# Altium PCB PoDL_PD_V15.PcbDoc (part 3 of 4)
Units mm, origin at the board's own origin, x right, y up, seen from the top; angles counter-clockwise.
Board outline 145 x 75 mm, 4 copper layers (Top Layer, Signal Layer 2, Signal Layer 3, Bottom Layer), stack 1.586 mm thick; 346 components, 228 nets, 1035 pads, 619 vias.
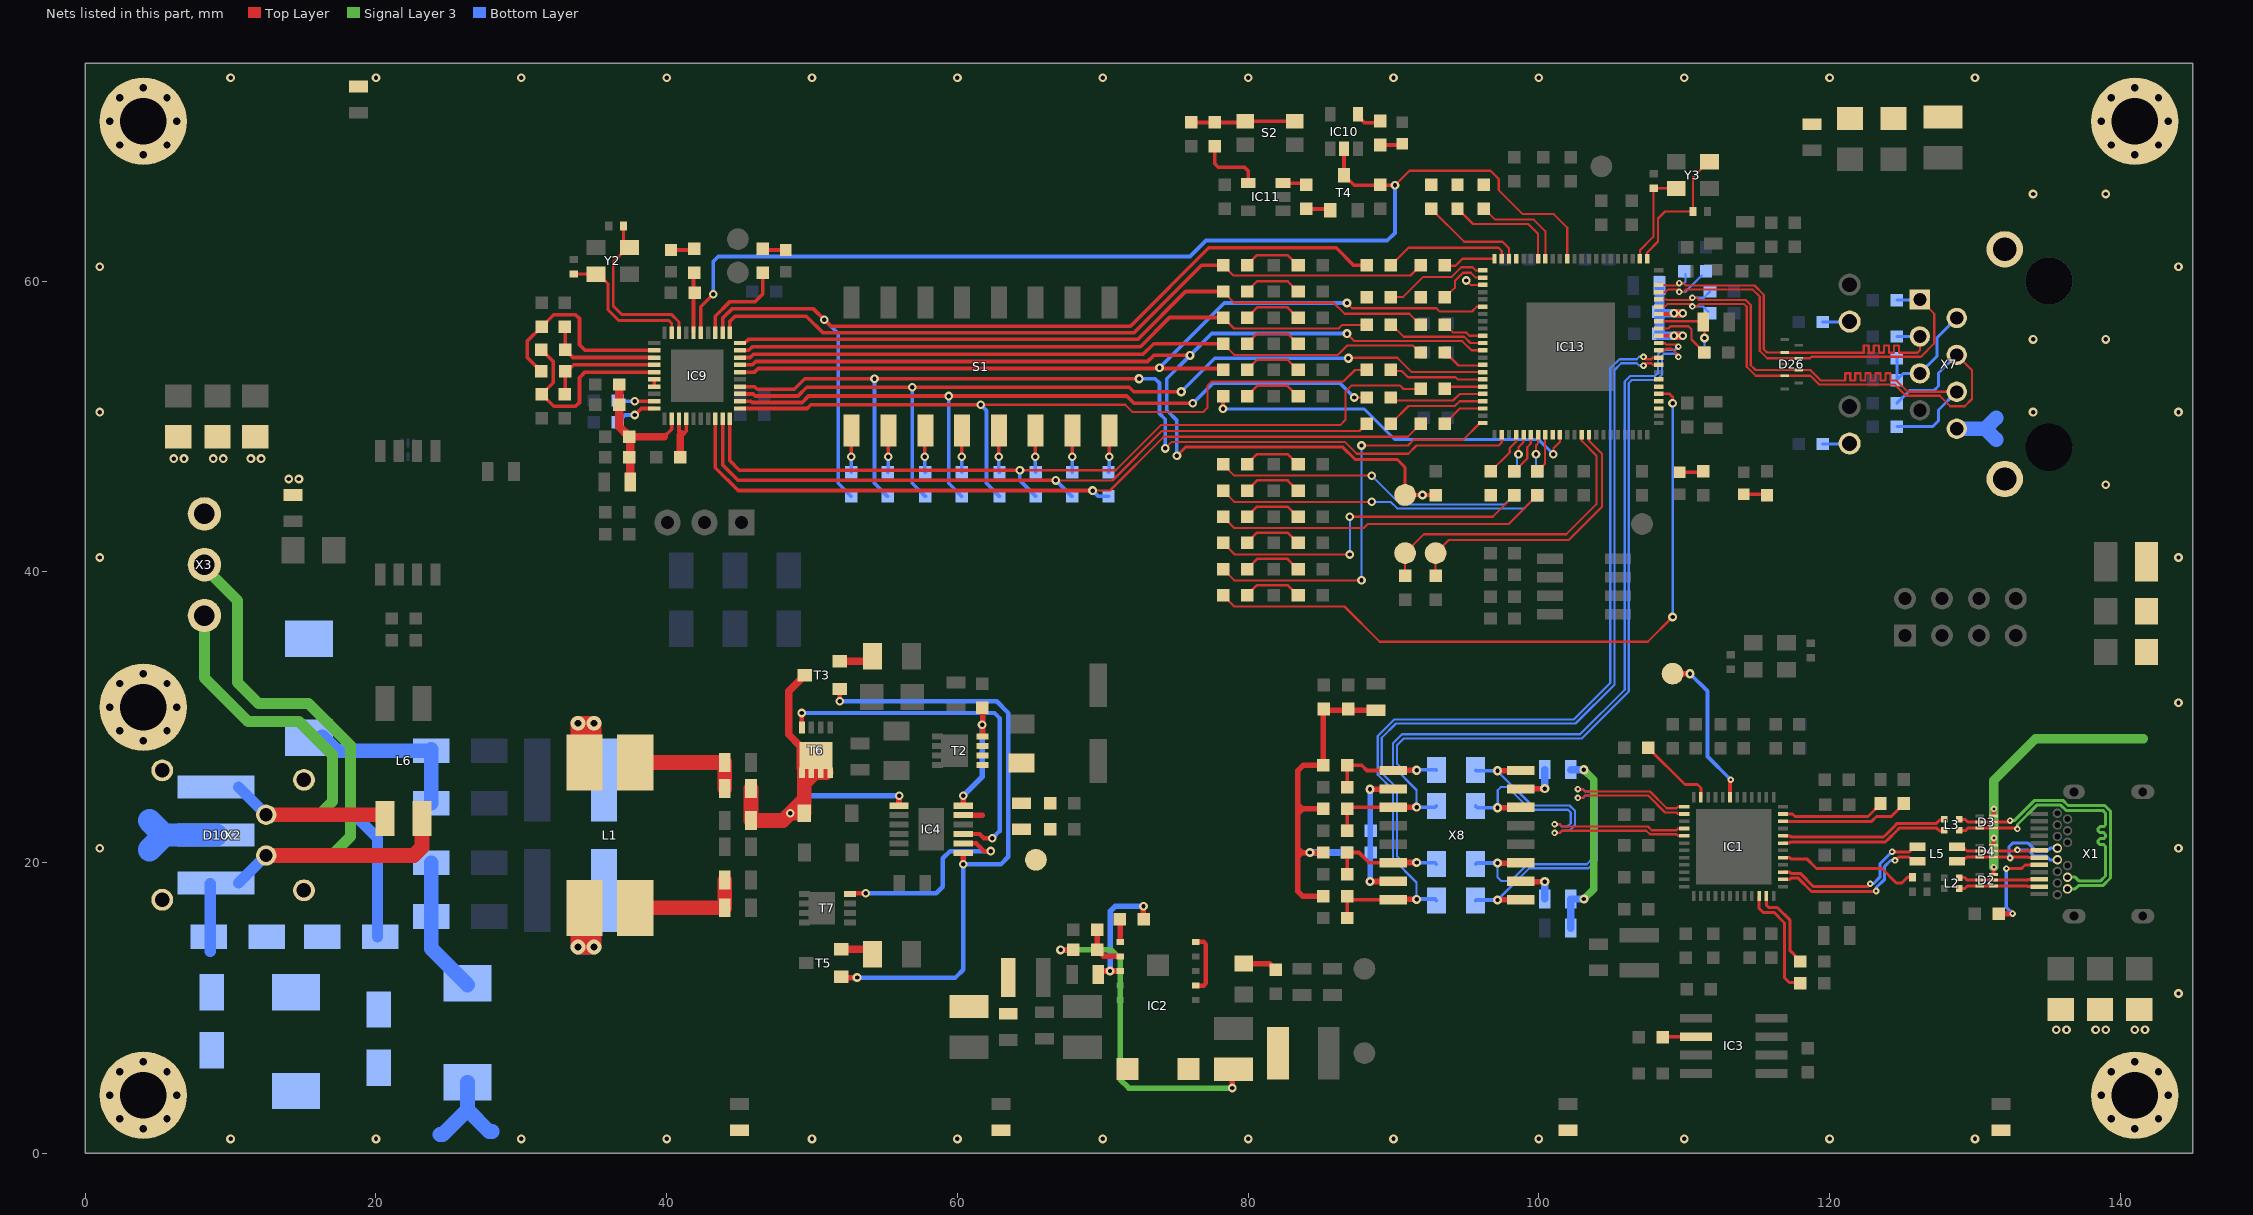
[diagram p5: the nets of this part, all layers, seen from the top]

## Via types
v1: diameter 0.6, hole 0.3, Top Layer to Bottom Layer, tented both sides, 350 vias
v2: diameter 0.45, hole 0.2, Top Layer to Bottom Layer, tented both sides, 137 vias
v3: diameter 0.635, hole 0.3, Top Layer to Bottom Layer, tented both sides, 77 vias
v4: diameter 1.016, hole 0.508, Top Layer to Bottom Layer, 40 vias
v5: diameter 1.016, hole 0.457, Top Layer to Bottom Layer, tented both sides, 8 vias
v6: diameter 0.762, hole 0.381, Top Layer to Bottom Layer, tented both sides, 7 vias

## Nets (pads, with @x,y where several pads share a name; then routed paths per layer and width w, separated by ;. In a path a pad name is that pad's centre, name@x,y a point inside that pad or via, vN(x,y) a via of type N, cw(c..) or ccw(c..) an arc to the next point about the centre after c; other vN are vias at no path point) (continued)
NetC53_1: C53.1 C54.1 FB8.1 R153.2 R154.2 R155.2 R156.2 R157.2 | length 26.9
  Top Layer w0.381: C53.1@85.075,30.449 C53.1@85.2,30.575 85.275,30.5 FB8.1@88.8,30.5 ; R154.2@85.175,17.7 83.75,17.7 83.4,18.05 83.4,20.4 ; R155.2@85.175,20.7 v3(84.25,20.7) 83.7,20.7 ; R156.2@85.175,23.7 83.75,23.7 ; C53.1@85.175,30.449 R157.2@85.175,26.7 83.779,26.7 83.4,26.321 83.4,24.05 ; 83.4,20.4 83.4,21 ; 83.4,20.4 83.7,20.7 ; 83.4,21 83.4,23.35 ; 83.4,21 83.7,20.7 ; 83.4,23.35 83.4,24.05 ; 83.4,23.35 83.75,23.7 ; 83.4,24.05 83.75,23.7
  Bottom Layer w0.508: v3(84.25,20.7) R153.2@86.775,20.7
NetC55_2: C55.2 IC9.8 Y2.1 | length 11.9
  Top Layer w0.203: C55.2@37.025,63.8 37.025,62.75 Y2.1@37.45,62.325 37.325,62.325 36.325,61.325 36.325,58.3 36.925,57.7 40.35,57.7 40.85,57.2 IC9.8@40.85,56.45
NetC56_2: C56.2 IC9.9 Y2.3 | length 10
  Top Layer w0.203: C56.2@33.6,60.5 35.3,60.5 Y2.3@35.325,60.475 ; Y2.3@35.15,60.475 Y2.3@35.325,60.475 ; IC9.9@40.35,56.45 40.35,57.1 40.15,57.3 36.7,57.3 35.95,58.05 35.95,59.85 Y2.3@35.325,60.475
NetC57_1: C57.1 C58.1 C63.1 C64.1 FB1.2 IC9.16 IC9.17 IC9.22 | length 11.4
  Top Layer w0.254: IC9.17@39.15,52.75 IC9.16@39.15,53.25 ; 39.825,49.3 40.35,49.825 IC9.22@40.35,50.55
  Top Layer w0.508: C63.1@37.426,49.3 39.825,49.3
  Top Layer w0.584: C58.1@36.726,52.9 C57.1@36.726,51.5 36.726,50 C63.1@37.426,49.3 37.5,49.226 FB1.2@37.5,46.2
NetC59_1: C59.1 IC9.19 | length 2.5
  Top Layer w0.254: v1(37.8,51.75) IC9.19@39.15,51.75
  Bottom Layer w0.254: C59.1@36.626,51.8 36.676,51.75 v1(37.8,51.75)
NetC60_1: C60.1 IC9.20 | length 2.9
  Top Layer w0.254: v1(37.8,50.8) 38.25,51.25 IC9.20@39.15,51.25
  Bottom Layer w0.254: C60.1@36.626,50.3 37.126,50.8 v1(37.8,50.8)
NetC65_1: C65.1 IC9.23 IC9.24 | length 4
  Top Layer w0.254: IC9.23@40.85,50.55 40.85,49.65 41,49.5 41.174,49.5 41.35,49.676 IC9.24@41.35,50.55
  Top Layer w0.508: C65.1@40.926,47.9 40.926,49.426 41,49.5
NetC77_1: C77.1 FB2.2 IC13.81 | length 5.1
  Top Layer w0.152: IC13.81@108.258,57.25 FB2.2@111.25,57.25 ; FB2.2@111.374,57.3 111.4,57.275 v1(111.4,56.1)
  Bottom Layer w0.152: C77.1@111.4,55.225 v1(111.4,56.1)
NetC80_1: C80.1 C81.1 FB5.1 IC13.79 IC13.82 | length 9.9
  Top Layer w0.254: IC13.79@108.308,56.25 v1(109.3,56.25) ; IC13.82@108.308,57.75 v1@109.3,57.75
  Top Layer w0.6: v1(109.3,56.25) v1(109.9,56.25) ; v1(109.3,57.8) v1(109.9,57.8)
  Bottom Layer w0.6: C81.1@108.225,56.3 108.275,56.25 v1(109.3,56.25) v1(109.9,56.25) ; C80.1@108.225,57.8 108.275,57.75 C80.1@108.3,57.75 ; C80.1@108.3,57.8 v1(109.3,57.8) v1(109.9,57.8)
  Bottom Layer w0.7: C81.1@108.225,56.3 108.3,56.375 108.3,57.75 FB5.1@108.3,59.6
NetC82_2: C82.2 IC13.1 Y3.1 | length 9.6
  Top Layer w0.152: IC13.1@107.45,61.55 107.45,61.983 108.203,62.736 108.203,64.32 108.683,64.8 C82.2@110.6,64.8 110.6,67.15 111.675,68.225 Y3.1@111.75,68.225
NetC83_2: C83.2 IC13.2 Y3.3 | length 6.8
  Top Layer w0.152: IC13.2@106.95,61.55 106.95,62.123 107.879,63.052 C83.2@107.879,66.4 ; C83.2@107.9,66.4 109.425,66.4 Y3.3@109.45,66.375
NetC89_1: C89.1 R81.1 X7.P2 X7.P5 | length 8.2
  Bottom Layer w0.203: R81.1@124.625,54.7 C89.1@124.625,53.2 125.09,53.665 X7.P5@126.21,53.665 ; X7.P5@126.145,53.6 X7.P5@126.21,53.665 ; X7.P2@128.75,57.475 127.4,56.125 127.4,54.855 X7.P5@126.21,53.665
NetC96_1: C96.1 FB10.1 IC4.11 R13.1 T2.1 T2.2 T2.3 | length 1.3
  Top Layer w0.381: IC4.11@60.416,23.275 61.7,23.275
NetC98_1: C98.1 R153.1 X8.10 X8.15 | length 9.5
  Top Layer w0.381: v3(88.388,18.706) X8.15@89.97,18.706 ; v3(88.388,25.056) X8.10@89.97,25.056
  Bottom Layer w0.381: v3(88.388,18.706) v3(88.388,25.056)
NetC103_1: C103.1 R158.1 R159.1 | length 13.3
  Signal Layer 3 w0.508: v3(103.1,17.5) 103.775,18.175 103.775,25.725 v3(103.1,26.4)
  Bottom Layer w0.508: C103.1@102.2,15.5 R158.1@102.2,17.5 ; R158.1@102.2,17.5 v3(103.1,17.5) ; R159.1@102.2,26.4 v3(103.1,26.4)
NetC106_1: C106.1 IC2.6 IC2.7 L12.1 R24.2 | length 22.7
  Top Layer w0.381: v1(67.1,14) R24.2@67.974,14 ; v1(78.9,4.5) C106.1@78.9,5.7
  Signal Layer 3 w0.381: v1(67.1,14) 70.6,14 71.2,13.4 71.2,5.1 71.8,4.5 v1(78.9,4.5)
NetC107_1: C107.1 IC2.3 R25.2 | length 9
  Top Layer w0.381: C107.1@69.7,12.3 69.95,12.55 v1(70.5,12.55) IC2.3@71.2,12.55 ; R25.2@72.8,16.125 v1(72.8,17)
  Bottom Layer w0.381: v1(70.5,12.55) 70.5,16.656 70.844,17 v1(72.8,17)
NetD1_1: D1.1 FB9.2 IC4.1 R3.1 T3.3 T6.mb | length 30.3
  Top Layer w0.381: IC4.1@55.984,23.925 55.984,24.584 v1(56,24.6)
  Top Layer w0.508: T6.mb@49.2,26.5 49.2,28.023 48.4,28.823 48.4,31.8 T3.3@49.5,32.9
  Top Layer w1.016: FB9.2@45.8,25.1 R3.1@45.8,22.9 48,22.9 v1(48.5,23.4) ; T6.mb@50.275,27.37 T6.mb@49.46,26.555 ; 50.97,26.19 T6.mb@50.6,26.19 50.191,26.19 ; v1(48.5,23.4) 49.4,24.3 49.46,24.3 ; v1(48.5,23.4) D1.1@49.46,23.4 49.46,24.3 ; 49.46,24.3 49.46,25.459 ; 49.46,25.459 50.191,26.19 ; 49.46,25.459 T6.mb@49.46,26.555 ; T6.mb@49.46,26.555 49.825,26.19 T6.mb@49.95,26.19 50.191,26.19
  Bottom Layer w0.381: v1(48.5,23.4) 49.7,24.6 v1(56,24.6)
NetD5_2: D5.2 R4.2 | length 2.4
  Top Layer w0.381: D5.2@79.7,13.05 81.476,13.05 R4.2@81.9,12.625
NetD11_1: D11.1 D13.2 D16.1
NetD12_2: D12.2 D13.1 D15.2
NetD14_2: D14.2 D18.1 D19.2 | length 9.4
  Bottom Layer w1.016: D14.2@23.8,20 D18.1@23.8,16.3 23.8,14.096 D19.2@26.3,11.596
NetD20_2: D20.2 D21.1 D31.2 | length 11.7
  Bottom Layer w1.016: D31.2@16.3,28.65 17.25,27.7 D20.2@23.8,27.7 23.8,27.8 D21.1@23.8,24.1
NetD23_1: D23.1 R62.1 | length 1.6
  Top Layer w0.254: D23.1@40.3,62.15 41.825,62.15 R62.1@41.9,62.226
NetD24_1: D24.1 R63.2 | length 1.6
  Top Layer w0.254: R63.2@46.6,62.226 46.676,62.15 D24.1@48.2,62.15
NetD25_2: D25.2 R74.2 | length 1.5
  Top Layer w0.254: R74.2@89.1,69.374 90.525,69.374 D25.2@90.6,69.45
NetD27_2: D27.2 R92.2 | length 1.6
  Top Layer w0.25: D27.2@114.1,45.35 115.624,45.35 R92.2@115.7,45.275
NetD28_2: D28.2 R93.2 | length 1.6
  Top Layer w0.25: D28.2@109.7,46.85 111.224,46.85 R93.2@111.3,46.926
NetIC1_23: IC1.23 R5.2 | length 5.8
  Top Layer w0.203: IC1.23@115.65,17.7 115.65,17.086 115.811,16.925 116.399,16.925 117.288,16.036 117.288,13.942 R5.2@117.975,13.255
NetIC1_35: IC1.35 R6.2 | length 7.2
  Top Layer w0.203: IC1.35@116.8,23.35 117.45,23.35 117.62,23.18 122.651,23.18 R6.2@123.525,24.055
NetIC1_47: IC1.47 R7.1 | length 5.4
  Top Layer w0.2: R7.1@107.526,27.9 110.045,25.381 110.905,25.381 111.15,25.135 IC1.47@111.15,24.5
NetIC2_1: IC2.1 R25.1 | length 1.5
  Top Layer w0.381: IC2.1@71.2,14.55 R25.1@71.2,16.074
NetIC2_2: IC2.2 R24.1 R26.1 | length 3.2
  Top Layer w0.381: R26.1@69.625,15.4 R24.1@69.625,14 70.076,13.55 IC2.2@71.2,13.55
NetIC2_9: IC2.9 IC2.12 | length 4.2
  Top Layer w0.305: IC2.9@76.4,11.55 76.95,11.55 77.1,11.7 77.1,14.4 76.95,14.55 IC2.12@76.4,14.55
NetIC3_6: IC3.6 R17.1 | length 2.2
  Top Layer w0.254: R17.1@108.56,8.035 IC3.6@110.8,8.035
NetIC4_7: IC4.7 T3.1 T5.1 | length 42.5
  Top Layer w0.305: v1(51.9,31.1) T3.1@51.9,31.95
  Top Layer w0.381: T5.1@52.15,12.1 v1(53.1,12.1) ; v1(60.4,19.9) 60.4,20.659 IC4.7@60.416,20.675
  Bottom Layer w0.305: v1(51.9,31.1) 62.7,31.1 63.5,30.3 63.5,20.405 62.995,19.9 v1(60.4,19.9) 60.4,12.635 59.865,12.1 v1(53.1,12.1)
NetIC4_8: IC4.8 T7.4 | length 14.1
  Top Layer w0.305: T7.4@52.6,17.9 v1(53.7,17.9) ; IC4.8@60.416,21.325 61.3,21.325 61.825,20.8 v1(62.3,20.8)
  Bottom Layer w0.305: v1(53.7,17.9) 58.545,17.9 59,18.355 59,20.3 59.5,20.8 v1(62.3,20.8)
NetIC4_9: IC4.9 T6.4 | length 25.3
  Top Layer w0.305: T6.4@49.3,29.3 v1(49.3,30.3) ; IC4.9@60.416,21.975 61.527,21.975 61.827,21.675 v1(62.4,21.675)
  Bottom Layer w0.305: v1(49.3,30.3) 62.553,30.3 62.9,29.953 62.9,22.175 v1(62.4,21.675)
NetIC4_12: IC4.12 R10.1 T2.4 | length 8.1
  Top Layer w0.381: IC4.12@60.4,23.941 v1(60.4,24.6) ; R10.1@61.7,30.675 61.73,30.645 T2.4@61.73,28.675
  Bottom Layer w0.381: v1(60.4,24.6) 61.7,25.9 v1(61.7,29.5)
NetIC9_3: IC9.3 R63.1 | length 6.5
  Top Layer w0.254: IC9.3@43.35,56.45 43.35,57.6 44.35,58.6 46.1,58.6 46.6,59.1 R63.1@46.6,60.575
NetIC9_6: IC9.6 R61.1 R62.2 | length 4.1
  Top Layer w0.254: IC9.6@41.85,56.45 41.85,60.525 R62.2@41.9,60.575
NetIC9_12: IC9.12 R64.2 R66.1 | length 14.1
  Top Layer w0.254: R66.1@31.375,53.8 30.4,54.775 30.4,55.875 R64.2@31.4,56.875 32.225,57.7 33.735,57.7 34,57.435 34,55.625 34.375,55.25 IC9.12@39.15,55.25
NetIC9_13: IC9.13 R65.2 R67.1 | length 7.7
  Top Layer w0.254: R65.2@33,56.875 33.026,56.849 R67.1@33.026,55.3 ; R67.1@33.2,55.1 33.55,54.75 IC9.13@39.15,54.75
NetIC9_14: IC9.14 R66.2 R68.2 | length 7.9
  Top Layer w0.254: R68.2@33,52.226 33.026,52.251 R66.2@33.026,53.8 33.15,53.8 33.6,54.25 IC9.14@39.15,54.25
NetIC9_15: IC9.15 R67.2 R69.2 | length 13.8
  Top Layer w0.254: R67.2@31.375,55.3 32.2,54.474 32.2,53.026 R69.2@31.4,52.226 32.226,51.4 33.735,51.4 34,51.665 34,53.364 34.386,53.75 IC9.15@39.15,53.75
NetIC10_4: IC10.4 R74.1 | length 1.9
  Top Layer w0.254: IC10.4@87.55,71.5 87.55,71.35 88,70.9 88.975,70.9 R74.1@89.1,71.025
NetIC11_3: IC11.3 R76.1 | length 1.7
  Top Layer w0.254: IC11.3@82.4,66.75 83.875,66.75 R76.1@84,66.626
NetIC11_4: IC11.4 R75.2 | length 4.5
  Top Layer w0.254: R75.2@77.7,69.274 77.7,68.1 77.95,67.85 79.75,67.85 80,67.6 IC11.4@80,66.75
NetIC13_15: IC13.15 R112.1 | length 6.8
  Top Layer w0.147: R112.1@96.231,64.998 96.993,64.236 99.66,64.236 100.45,63.446
  Top Layer w0.152: IC13.15@100.45,61.55 100.45,63.446
NetIC13_16: IC13.16 R113.1 | length 7.9
  Top Layer w0.152: R113.1@94.434,64.974 95.474,63.934 99.262,63.934 99.95,63.245 IC13.16@99.95,61.55
NetIC13_20: IC13.20 R120.1 | length 7.2
  Top Layer w0.152: R120.1@92.6,64.975 94.862,62.712 97.499,62.712 97.95,62.261 IC13.20@97.95,61.55
NetIC13_21: IC13.21 R131.2 | length 8.8
  Top Layer w0.152: R131.2@89.825,61.1 91.032,62.307 97.228,62.307 97.45,62.085 IC13.21@97.45,61.55
NetIC13_22: IC13.22 R130.2 | length 3.6
  Top Layer w0.152: R130.2@93.572,61.064 94.264,61.064 94.75,61.55 IC13.22@96.95,61.55
NetIC13_23: IC13.23 R115.1 | length 7.2
  Top Layer w0.147: R115.1@89.889,58.905 90.646,58.905 ; 94.002,60.302 94.661,60.961 95.439,60.961 95.65,60.75 IC13.23@96.15,60.75
  Top Layer w0.152: 90.646,58.905 92.043,60.302 94.002,60.302
NetIC13_24: IC13.24 R117.1 | length 3.7
  Top Layer w0.152: R117.1@93.572,58.905 94.224,59.556 94.224,60.024 94.78,60.58 95.32,60.58 95.65,60.25 IC13.24@96.15,60.25
NetIC13_32: IC13.32 R128.2 | length 2.9
  Top Layer w0.147: R128.2@93.572,57 94.086,56.485 94.984,56.485 95.22,56.25 IC13.32@96.15,56.25
NetIC13_33: IC13.33 R126.2 | length 6.8
  Top Layer w0.152: R126.2@89.889,57 90.705,56.183 94.859,56.183 95.292,55.75 IC13.33@96.15,55.75
NetIC13_36: IC13.36 R124.2 | length 2.7
  Top Layer w0.152: R124.2@93.572,55.095 94.467,54.2 IC13.36@95.95,54.2
NetIC13_38: IC13.38 R119.2 | length 6.5
  Top Layer w0.147: R119.2@89.889,53.825 90.575,53.825 91,53.4 94.264,53.4 94.414,53.25 94.782,53.25
  Top Layer w0.152: 94.782,53.25 IC13.38@96.15,53.25
NetIC13_39: IC13.39 R118.2 | length 2.4
  Top Layer w0.152: R118.2@93.767,52.75 IC13.39@96.15,52.75
NetIC13_40: IC13.40 R121.2 | length 6.3
  Top Layer w0.152: R121.2@90.016,51.793 94.093,51.793 94.55,52.25 IC13.40@96.15,52.25
NetIC13_41: IC13.41 R116.2 | length 6.9
  Top Layer w0.152: R116.2@89.889,50.269 91.032,51.412 94.221,51.412 94.559,51.75 IC13.41@96.15,51.75
NetIC13_42: IC13.42 R114.2 | length 2.9
  Top Layer w0.147: R114.2@93.621,50.307 94.564,51.25 95.477,51.25
  Top Layer w0.152: 95.477,51.25 IC13.42@96.15,51.25
NetIC13_48: IC13.48 R129.1 | length 3.2
  Top Layer w0.152: R129.1@96.7,46.925 98,48.225 98,48.525 98.45,48.975 IC13.48@98.45,49.45
NetIC13_49: IC13.49 R127.1 | length 2.7
  Top Layer w0.152: v1(98.6,48.1) 98.6,48.572 98.95,48.922 IC13.49@98.95,49.45
  Bottom Layer w0.147: R127.1@98.2,47.026 R127.1@98.4,47.226
  Bottom Layer w0.152: R127.1@98.5,47.226 v1@98.5,48.1
NetIC13_50: IC13.50 R122.1 | length 3.3
  Top Layer w0.152: R122.1@97.99,47.121 R122.1@98.27,47.121 ; R122.1@98.3,46.9 99.2,47.8 99.2,48.59 99.45,48.84 IC13.50@99.45,49.45
NetIC13_51: IC13.51 R125.1 | length 2.5
  Top Layer w0.152: v1(99.8,48.1) 99.8,48.7 99.95,48.85 IC13.51@99.95,49.45
  Bottom Layer w0.152: R125.1@99.8,47.026 v1(99.8,48.1)
NetIC13_52: IC13.52 R123.1 | length 2.8
  Top Layer w0.152: R123.1@99.9,46.925 100.421,47.446 100.421,49.421 IC13.52@100.45,49.45
NetL1_2: L1.2 L10.1 | length 5.2
  Top Layer w1.016: L1.2@33.9,28.345 v5(33.9,29.6) v5@33.95,29.6 ; L1.2@34.4,27.9 34.4,29.15 v5@33.95,29.6 ; L1.2@35,28.6 v5(35,29.6) v5@33.95,29.6
NetL1_3: L1.3 L8.1 | length 6.3
  Top Layer w1.016: L1.3@33.9,15.2 v5(33.9,14.2) v5@34.95,14.2 ; L1.3@34.5,15.9 34.5,14.65 v5@34.95,14.2 ; L1.3@35,15.455 v5(35,14.2) v5@34.95,14.2
  Bottom Layer w1.016: v5(33.9,14.2) 34,14.2 v5(35,14.2)
NetR2_1: R2.1 X1.A5 | length 6.6
  Top Layer w0.203: v2(132.161,19.589) 133.189,19.589 133.45,19.85 X1.A5@134.42,19.85
  Top Layer w0.381: R2.1@131.671,16.5 v2(132.595,16.5)
  Bottom Layer w0.254: v2(132.161,19.589) 132.161,16.939 v2@132.595,16.505
NetR14_1: R14.1 T5.2 | length 2
  Top Layer w0.508: T5.2@52,14.05 R14.1@54,14.05
NetR15_1: R15.1 T3.2 | length 2.4
  Top Layer w0.381: R15.1@53.8,33.85 R15.1@54.15,34.2
  Top Layer w0.508: T3.2@51.9,33.85 R15.1@53.8,33.85
NetR52_2: R52.2 S1.1 | length 2.9
  Top Layer w0.254: v1(52.7,47.925) 52.7,49.695 S1.1@52.73,49.725
  Bottom Layer w0.254: R52.2@52.7,46.851 v1(52.7,47.925)
NetR53_2: R53.2 S1.2 | length 2.9
  Top Layer w0.254: v1(55.24,47.925) S1.2@55.24,49.695
  Bottom Layer w0.254: R53.2@55.2,46.851 55.24,46.891 v1(55.24,47.925)
NetR54_2: R54.2 S1.3 | length 2.9
  Top Layer w0.254: v1(57.76,47.925) S1.3@57.76,49.695
  Bottom Layer w0.254: v1(57.76,47.925) 57.76,46.891 R54.2@57.8,46.851
NetR55_2: R55.2 S1.4 | length 2.8
  Top Layer w0.254: v1(60.3,47.925) S1.4@60.3,49.695
  Bottom Layer w0.254: R55.2@60.3,46.851 v1(60.3,47.925)
NetR56_2: R56.2 S1.5 | length 2.9
  Top Layer w0.254: v1(62.84,47.925) S1.5@62.84,49.695
  Bottom Layer w0.254: v1(62.84,47.925) 62.84,46.911 R56.2@62.9,46.851
NetR57_2: R57.2 S1.6 | length 2.9
  Top Layer w0.254: v1(65.36,47.925) S1.6@65.36,49.695
  Bottom Layer w0.254: v1(65.36,47.925) 65.36,46.891 R57.2@65.4,46.851
NetR58_2: R58.2 S1.7 | length 2.8
  Top Layer w0.254: v1(67.9,47.925) S1.7@67.9,49.695
  Bottom Layer w0.254: R58.2@67.9,46.851 v1(67.9,47.925)
NetR59_2: R59.2 S1.8 | length 2.9
  Top Layer w0.254: v1(70.44,47.925) S1.8@70.44,49.695
  Bottom Layer w0.254: R59.2@70.4,46.851 70.44,46.891 v1(70.44,47.925)
NetR73_1: R73.1 R75.1 S2.2 S2.4 | length 7.5
  Top Layer w0.254: R73.1@76.1,70.925 R75.1@77.7,70.925 79.375,70.925 79.45,71 S2.2@83.55,71
NetR76_2: R76.2 T4.1 | length 1.7
  Top Layer w0.254: R76.2@84,64.975 85.576,64.975 T4.1@85.65,64.9
NetR90_1: R90.1 X7.P10 | length 1.9
  Bottom Layer w0.203: R90.1@119.525,57.2 121.355,57.2 X7.P10@121.38,57.225
NetR91_1: R91.1 X7.P12 | length 1.9
  Bottom Layer w0.203: R91.1@119.525,48.8 121.345,48.8 X7.P12@121.38,48.835
NetR94_1: R94.1 R100.2 R106.2 | length 4.1
  Top Layer w0.178: R100.2@79.925,61.1 80.626,61.8 82.725,61.8 R106.2@83.425,61.1
NetR95_1: R95.1 R101.2 R107.2 | length 4.1
  Top Layer w0.178: R101.2@79.925,59.3 80.626,60 82.725,60 R107.2@83.425,59.3
NetR96_1: R96.1 R102.2 R108.2 | length 4.1
  Top Layer w0.178: R102.2@79.925,57.5 80.626,58.2 82.725,58.2 R108.2@83.425,57.5
NetR97_1: R97.1 R103.2 R109.2 | length 4.1
  Top Layer w0.178: R103.2@79.925,55.7 80.626,56.4 82.725,56.4 R109.2@83.425,55.7
NetR98_1: R98.1 R104.2 R110.2 | length 4.1
  Top Layer w0.178: R104.2@79.925,52.1 80.626,52.8 82.725,52.8 R110.2@83.425,52.1
NetR99_1: R99.1 R105.2 R111.2 | length 4.1
  Top Layer w0.178: R105.2@79.925,53.9 80.626,54.6 82.725,54.6 R111.2@83.425,53.9
NetR132_1: R132.1 R138.2 R144.2 | length 4.1
  Top Layer w0.178: R138.2@79.925,47.4 80.626,48.1 82.725,48.1 R144.2@83.425,47.4
NetR133_1: R133.1 R139.2 R145.2 | length 4.1
  Top Layer w0.178: R139.2@79.925,45.6 80.626,46.3 82.725,46.3 R145.2@83.425,45.6
NetR134_1: R134.1 R140.2 R146.2 | length 4.1
  Top Layer w0.178: R140.2@79.925,43.8 80.626,44.5 82.725,44.5 R146.2@83.425,43.8
NetR135_1: R135.1 R141.2 R147.2 | length 4.1
  Top Layer w0.178: R141.2@79.925,42 80.626,42.7 82.725,42.7 R147.2@83.425,42
NetR136_1: R136.1 R142.2 R148.2 | length 4.1
  Top Layer w0.178: R142.2@79.925,38.4 80.626,39.1 82.725,39.1 R148.2@83.425,38.4
NetR137_1: R137.1 R143.2 R149.2 | length 4.1
  Top Layer w0.178: R143.2@79.925,40.2 80.626,40.9 82.725,40.9 R149.2@83.425,40.2
NetR158_2: R158.2 X8.2 | length 2.8
  Top Layer w0.381: X8.2@98.779,18.744 98.823,18.7 v3(100.4,18.7)
  Bottom Layer w0.508: R158.2@100.4,17.5 v3(100.4,18.7)
NetR159_2: R159.2 X8.7 | length 3
  Top Layer w0.381: X8.7@98.74,25.056 98.784,25.1 v3(100.4,25.1)
  Bottom Layer w0.508: v3(100.4,25.1) R159.2@100.4,26.4
P0_COL: IC13.70
P0_CRS: IC13.69
P0_DUPLEX: IC13.54 R104.1 | length 26.4
  Top Layer w0.152: v1(101,48.1) 101,48.5 101.45,48.95 IC13.54@101.45,49.45
  Top Layer w0.3: v1(78.274,51.226) R104.1@78.274,52.1
  Bottom Layer w0.203: v1(78.274,51.226) 87.975,51.226 90.1,49.1 100,49.1 v1(101,48.1)
P0_INCLK: IC9.32 R55.1 R121.1 | length 51.9
  Top Layer w0.147: v1(87.3,52) R121.1@88.174,52 R121.1@88.174,52.105
  Top Layer w0.254: IC9.32@45.05,51.75 45.8,51.75 45.885,51.665 49.329,51.665 49.764,52.1 v1(59.4,52.1) 71.655,52.1 72.155,51.6 v1(76.2,51.6)
  Bottom Layer w0.254: v1(59.4,52.1) 59.4,46.1 R55.1@60.3,45.2 ; v1(76.2,51.6) 77.6,53 86.3,53 v1(87.3,52)
P0_IND0: IC9.31 R56.1 R119.1 | length 52.4
  Top Layer w0.147: v1(61.6,51.5) 71.554,51.5 72.054,51 76.9,51 77.2,51.3 77.2,52.8 77.5,53.1 86.556,53.1 87.356,53.9 R119.1@88.2,53.9
  Top Layer w0.254: IC9.31@45.05,51.25 49.664,51.25 49.914,51.5 v1(61.6,51.5)
  Bottom Layer w0.254: v1(61.6,51.5) 62,51.1 62,46.1 R56.1@62.9,45.2
P0_IND1: IC9.30 R57.1 R118.1 | length 56.7
  Top Layer w0.147: v1(64.3,47) 70.9,47 74,50.1 86.338,50.1 86.7,50.462 86.7,52.4 87.139,52.839 90.436,52.839 90.684,52.592 91.709,52.592 R118.1@91.857,52.74
  Top Layer w0.254: IC9.30@44.35,50.55 44.35,47.65 45,47 v1(64.3,47)
  Bottom Layer w0.254: v1(64.3,47) 64.3,46.3 R57.1@65.4,45.2
P0_IND2: IC9.29 R58.1 R116.1 | length 51.1
  Top Layer w0.152: v1(66.775,46.3) 70.67,46.3 74.065,49.695 87.67,49.695 R116.1@88.174,50.2
  Top Layer w0.254: IC9.29@43.85,50.55 43.85,47.375 44.925,46.3 v1(66.775,46.3)
  Bottom Layer w0.254: v1(66.775,46.3) 67.875,45.2 R58.1@67.9,45.2
P0_IND3: IC9.28 R59.1 R114.1 | length 55.7
  Top Layer w0.152: v1(69.3,45.6) 70.5,45.6 74.2,49.3 90.974,49.3 R114.1@91.874,50.2
  Top Layer w0.254: IC9.28@43.35,50.55 43.35,47.176 44.926,45.6 v1(69.3,45.6)
  Bottom Layer w0.254: v1(69.3,45.6) 69.7,45.2 R59.1@70.4,45.2
P0_INDV: IC9.33 IC13.37 R54.1 | length 60.8
  Top Layer w0.147: v3@86.9,54.738 90.262,54.738 91.25,53.75 IC13.37@96.15,53.75
  Top Layer w0.254: IC9.33@45.05,52.25 45.95,52.25 46.1,52.1 49.034,52.1 49.634,52.7 v1(56.9,52.7) 71.83,52.7 72.13,52.4 v3(75.4,52.4)
  Bottom Layer w0.254: v1(56.9,52.7) 56.9,46.1 R54.1@57.8,45.2 ; v3(75.4,52.4) 77.7,54.7 v3(86.9,54.7)
P0_INER: IC9.34 IC13.46 R53.1 | length 67
  Top Layer w0.152: v1(74.3,48.5) 74.75,48.95 86.645,48.95 87.463,48.131 91.012,48.131 91.58,48.7 97.247,48.7 97.45,48.903 IC13.46@97.45,49.45
  Top Layer w0.254: IC9.34@45.05,52.75 46.05,52.75 46.225,52.575 48.775,52.575 49.5,53.3 v1(54.3,53.3) v3(72.5,53.3)
  Bottom Layer w0.254: v1(54.3,53.3) 54.3,46.1 R53.1@55.2,45.2 ; v3(72.5,53.3) 73.6,53.3 73.9,53 73.9,50.9 74.3,50.5 v1(74.3,48.5)
P0_MDC: IC13.57 R151.2 TP8.1 | length 21.3
  Top Layer w0.152: R151.2@90.8,39.726 TP8.1@90.8,41.3 92.092,42.592 101.888,42.592 103.959,44.663 103.959,48.01 102.95,49.019 IC13.57@102.95,49.45
P0_MDIO: IC13.58 R150.1 TP7.1 | length 19.7
  Top Layer w0.152: R150.1@92.9,39.726 TP7.1@92.9,41.3 93.8,42.2 102.05,42.2 104.34,44.49 104.34,48.137 103.45,49.027 IC13.58@103.45,49.45
P0_OUT/REF_CLK_MODE0: IC9.38 R103.1 R124.1 | length 48.2
  Top Layer w0.147: R103.1@78.274,55.7 79.039,54.935 86.185,54.935 86.831,55.581 91.323,55.581 91.809,55.095 R124.1@92.048,55.095
  Top Layer w0.254: IC9.38@45.05,54.75 45.75,54.75 45.975,54.975 72.775,54.975 73.5,55.7 R103.1@78.274,55.7
P0_OUTD0_MODE1: IC9.39 R102.1 R126.1 | length 44.5
  Top Layer w0.152: R102.1@78.274,57.5 79.024,56.75 86.225,56.75 86.475,57 R126.1@88.174,57
  Top Layer w0.254: IC9.39@45.05,55.25 45.65,55.25 45.9,55.5 72.6,55.5 74.6,57.5 R102.1@78.274,57.5
P0_OUTD1_MODE2: IC9.40 R101.1 R128.1 | length 48.9
  Top Layer w0.147: R101.1@78.274,59.3 79.049,58.526 85.874,58.526 86.638,57.762 91.088,57.762 R128.1@91.6,57.25
  Top Layer w0.254: IC9.40@45.05,55.75 45.375,55.75 45.625,56 72.4,56 75.7,59.3 R101.1@78.274,59.3
P0_OUTD2_MODE3: IC9.1 R100.1 R130.1 | length 51.5
  Top Layer w0.147: R100.1@78.274,61.1 78.974,60.4 91.174,60.4 R130.1@91.874,61.1
  Top Layer w0.254: IC9.1@44.35,56.45 44.35,57.25 44.7,57.6 49.6,57.6 50.75,56.45 72.15,56.45 76.8,61.1 R100.1@78.274,61.1
P0_OUTD3: IC9.2 R52.1 R131.1 | length 61.7
  Top Layer w0.254: IC9.2@43.85,56.45 43.85,57.45 44.5,58.1 50.1,58.1 v1(50.85,57.35) 51.3,56.9 71.9,56.9 77.3,62.3 86.056,62.3 87.256,61.1 R131.1@88.174,61.1
  Bottom Layer w0.254: v1(50.85,57.35) 51.8,56.4 51.8,46.1 R52.1@52.7,45.2
P0_OUTDV: IC9.37 IC13.34 R152.2 TP9.1 | length 80.8
  Top Layer w0.147: v3(86.8,56.4) 87.319,55.881 94.734,55.881 95.365,55.25 IC13.34@96.15,55.25
  Top Layer w0.203: v1(75.1,48) 75.685,48.585 86.515,48.585 87.35,47.75 90.25,47.75 90.8,47.2 TP9.1@90.8,45.3
  Top Layer w0.254: IC9.37@45.05,54.25 45.906,54.25 46.13,54.474 73.074,54.474 73.5,54.9 v3(76,54.9) ; TP9.1@90.8,45.3 v1(92,45.3) 92.874,45.3 R152.2@92.9,45.274
  Bottom Layer w0.254: v1(75.1,48) 75.1,50.423 74.4,51.123 74.4,53.3 v3(76,54.9) 77.5,56.4 v3(86.8,56.4)
P0_OUTER_SPEED: IC9.36 IC13.28 R105.1 | length 57.8
  Top Layer w0.147: v1(86.8,58.5) 87.157,58.143 92.956,58.143 93.186,57.913
  Top Layer w0.152: 93.186,57.913 95.398,57.913 95.735,58.25 IC13.28@96.15,58.25
  Top Layer w0.254: IC9.36@45.05,53.75 46.045,53.75 46.295,54 R105.1@78.274,54
  Bottom Layer w0.254: v1(73.9,54.044) 78.356,58.5 v1(86.8,58.5)
P1_COL: IC13.72
P1_CRS: IC13.73
P1_IND0: R117.2
P1_IND1: R115.2
P1_IND2: R113.2
P1_IND3: R112.2
P1_INDCLK: R120.2
P1_INDV: IC13.25 | length 1.3
  Top Layer w0.147: v1(95.012,60.048) 95.31,59.75 IC13.25@96.15,59.75
P1_INER: IC13.19
P1_MDC_DUPLEX: IC13.71 R142.1 | length 49.1
  Top Layer w0.147: R142.1@78.274,38.4 79.049,37.626 86.628,37.626 89.053,35.2 107.5,35.2 v1(109.2,36.9)
  Top Layer w0.178: IC13.71@108.25,52.25 109,52.25 109.2,52.05 v1(109.2,51.6)
  Bottom Layer w0.178: v1(109.2,36.9) v1(109.2,51.6)
P1_OUT/REF_CLK_MODE0: R122.2 R141.1 | length 23.6
  Top Layer w0.147: R141.1@78.274,42 79.074,41.2 v1(87,41.2)
  Top Layer w0.152: v1(87,43.8) 96.825,43.8 R122.2@98.3,45.274
  Bottom Layer w0.147: v1(87,41.2) v1(87,43.8)
P1_OUTD0_MODE1: R123.2 R140.1 | length 23
  Top Layer w0.147: R140.1@78.274,43.8 79.049,43.026 87.951,43.026 88.225,43.3 97.925,43.3 R123.2@99.9,45.274
  Top Layer w0.203: R123.2@99.9,45.274 R123.2@99.9,45.375
P1_OUTD1_MODE2: R125.2 R139.1 | length 22.5
  Top Layer w0.147: R139.1@78.274,45.6 79.049,44.826 v1(88.5,44.826)
  Bottom Layer w0.147: v1(88.5,44.826) 89.799,44.826 90.25,44.375 99,44.375 R125.2@99.9,45.274
P1_OUTD2_MODE3: R127.2 R138.1 | length 21.4
  Top Layer w0.147: R138.1@78.274,47.4 79.049,46.626 v1(88.5,46.626)
  Bottom Layer w0.147: v1(88.5,46.626) 90.477,44.649 97.674,44.649 R127.2@98.3,45.274
P1_OUTD3: R129.2
P1_OUTDV: IC13.53
P1_OUTER_MDIO_SPEED: IC13.44 R143.1 | length 28.1
  Top Layer w0.147: R143.1@78.274,40.2 79.049,39.425 v1(87.8,39.425) ; IC13.44@95.95,50.25 IC13.44@96.15,50.25
  Top Layer w0.152: v1(87.8,48.7) 91,48.7 91.4,49.1 94.8,49.1 IC13.44@95.95,50.25
  Bottom Layer w0.147: v1(87.8,39.425) v1(87.8,48.7)
PME_MODE: IC1.43 TP1.1 | length 10.9
  Top Layer w0.25: IC1.43@113.15,24.5 v2@113.15,25.705
  Top Layer w0.381: TP1.1@109.2,33.005 v3(110.4,33.005)
  Bottom Layer w0.25: v3(110.4,33.005) 111.6,31.805 111.6,27.305 v2(113.2,25.705)
PME_N/CONNECT: IC1.22 R8.1 | length 8
  Top Layer w0.203: IC1.22@115.15,17.7 115.15,16.86 115.425,16.585 116.17,16.585 116.9,15.855 116.9,12.083 117.228,11.755 R8.1@117.975,11.755
POWER/DATA_N: D10.2 D15.1 D16.2 L6.4 X2.2 X3.1 | length 49.2
  Top Layer w1.016: X2.2@12.45,23.3 L6.4@20.6,23.3
  Signal Layer 3 w0.762: X3.1@8.2,36.8 8.2,32.7 11.2,29.7 14.712,29.7 17,27.412 17,24.2 16.1,23.3 X2.2@12.45,23.3
  Bottom Layer w0.762: D10.2@10.55,25.2 X2.2@12.45,23.3 18.5,23.3 20.1,21.7 D16.2@20.1,14.9
POWER/DATA_P: D10.1 D11.2 D12.1 L6.3 X2.1 X3.2 | length 51.3
  Top Layer w1.016: X2.1@12.45,20.5 22.62,20.5 23.17,21.05 L6.3@23.17,23.05
  Signal Layer 3 w0.762: X3.2@8.2,40.3 10.473,38.027 10.473,32.413 11.936,30.95 15.35,30.95 18.25,28.05 18.25,21.804 16.946,20.5 X2.1@12.45,20.5
  Bottom Layer w0.762: 8.6,13.9 D10.1@8.6,18.555 ; D10.1@10.55,18.6 X2.1@12.45,20.5
PWR+: C39.1 FB9.1 L1.1 | length 7.9
  Top Layer w1.016: L1.1@37.85,26.9 C39.1@44,26.9 FB9.1@44,25.1
PWR-: C44.1 FB12.1 L1.4 | length 8
  Top Layer w1.016: L1.4@37.85,16.9 C44.1@44,16.9 FB12.1@44,18.8
PWR_OUT: C25.1 C43.1 C97.1 FB10.2 L11.1 TP2.1
R\E\S\E\T\: IC9.5 IC10.2 IC13.12 R72.2 T4.3 | length 78.3
  Top Layer w0.152: v1(90.1,66.6) 91.1,67.6 96.677,67.6 97.247,67.03 97.247,66.268 98.898,64.617 101.021,64.617 101.95,63.688 IC13.12@101.95,61.55
  Top Layer w0.254: IC9.5@42.35,56.45 42.35,58.25 v1(43.2,59.1) ; IC10.2@86.6,69.1 T4.3@86.6,67.3 87.3,66.6 v1(90.1,66.6)
  Bottom Layer w0.254: v1(43.2,59.1) 43.2,61.356 43.544,61.7 76,61.7 77.1,62.8 89.574,62.8 90.1,63.326 v1(90.1,66.6)
RBIAS: IC13.80 R83.1 | length 4.3
  Top Layer w0.152: IC13.80@108.308,56.75 108.9,56.75 109.05,56.9 110.3,56.9 110.5,56.7 110.5,56 R83.1@111.4,55.1
RXA_N: C102.1 IC13.77 R157.1 R163.2 X8.9 | length 56
  Top Layer w0.154: IC13.77@108.25,55.25 108.652,55.25 108.761,55.36 109.134,55.36 109.6,54.894 v2(109.6,54.8)
  Top Layer w0.254: C102.1@86.826,25.2 R157.1@86.826,26.7 87.825,26.7 88.18,26.345 X8.9@89.989,26.345
  Top Layer w0.381: X8.9@90.009,26.364 v3(91.591,26.364)
  Bottom Layer w0.154: v3(91.591,26.364) 90.686,26.364 90.25,26.8 90.25,28.1 90.7,28.55 102.95,28.55 106.184,31.784 106.184,52.987 106.397,53.2 108.097,53.2 108.47,53.573 108.47,54.87 108.61,55.01 109.39,55.01 v2(109.6,54.8)
  Bottom Layer w0.254: v3@91.591,26.4 92.92,26.4 R163.2@92.95,26.37
RXA_P: C101.1 IC13.78 R156.1 R162.2 X8.11 | length 58.2
  Top Layer w0.154: IC13.78@108.25,55.75 108.652,55.75 108.761,55.64 109.46,55.64 v2(109.6,55.5)
  Top Layer w0.254: C101.1@86.826,22.2 R156.1@86.826,23.5 ; R156.1@86.826,23.7 86.826,23.805 X8.11@89.989,23.805
  Top Layer w0.381: X8.11@90.009,23.824 v3(91.591,23.824)
  Bottom Layer w0.154: v3@91.591,23.826 91.591,25.009 89.969,26.631 89.969,28.216 90.584,28.831 102.834,28.831 105.903,31.9 105.903,53.103 106.281,53.481 107.981,53.481 108.189,53.689 108.189,54.986 108.493,55.29 109.39,55.29 v2(109.6,55.5)
  Bottom Layer w0.254: v3@91.591,23.826 92.876,23.826 R162.2@92.95,23.9
RXB_N: C88.1 D26.7 IC13.84 R80.1 X7.P6 | length 37.6
  Top Layer w0.147: IC13.84@108.25,58.75 108.775,58.75 108.824,58.701 108.828,58.704 110.397,58.704 110.4,58.707 ; 111.019,58.707 114.231,58.707 114.574,58.364 114.574,54.226 114.9,53.9 D26.7@117.875,53.9 118.678,53.9 119.404,53.174 120.9,53.174 121.074,53.174 121.074,53.674 121.421,53.674 121.421,53.174 121.768,53.174 121.768,53.674 122.116,53.674 122.116,53.174 122.463,53.174 122.463,53.674 122.81,53.674 122.81,53.174 123.158,53.174 123.158,53.674 123.505,53.674 123.505,53.174 123.852,53.174 123.852,53.674 124.2,53.674 124.2,53.174 124.3,53.174 124.589,53.174 125.369,52.395 X7.P6@128.75,52.395
  Top Layer w0.154: 110.4,58.707 v2(110.56,58.867) 110.86,58.867 111.019,58.707
  Bottom Layer w0.154: v2(110.56,58.867) 111.341,58.867 C88.1@111.775,59.3
  Bottom Layer w0.203: R80.1@124.625,50 127.1,50 127.5,50.4 127.5,51.145 X7.P6@128.75,52.395
RXB_P: C87.1 D26.4 IC13.83 R79.1 X7.P4 | length 38.1
  Top Layer w0.147: IC13.83@108.25,58.25 108.649,58.25 108.825,58.426 110.4,58.426 ; 110.86,58.267 111.019,58.426 114.124,58.426 114.3,58.25 114.3,54.112 114.912,53.5 D26.4@116.925,53.5 118.69,53.5 119.29,52.9 124.476,52.9 125.255,52.121 127.579,52.121 128.3,51.4 129.3,51.4 129.8,51.9 129.8,53.885 X7.P4@128.75,54.935
  Top Layer w0.154: 110.4,58.426 v2(110.56,58.267) 110.86,58.267
  Bottom Layer w0.154: v2(110.56,58.267) 111.296,58.267 C87.1@111.663,57.9
  Bottom Layer w0.203: R79.1@124.625,51.6 125.525,52.5 127.2,52.5 127.5,52.8 127.5,53.685 X7.P4@128.75,54.935 X7.P4@128.785,54.9
SHIELD: C19.2 C42.1 C90.1 C91.1 C92.1 C93.1 C94.1 C95.1 C104.1 C108.2 D2.3 D3.3 D4.3 D10.3 D19.1 D31.1 H1.0 H2.0 H3.0 H4.0 H5.0 R16.2 R19.2 R20.2 R21.2 R22.2 R23.2 R27.2 VAR1.2 VAR2.1 X2.SH X3.3 X7.B1 X7.B2 X7.P8 | length 39.7
  Top Layer w0.254: 131.275,19.3 v2@131.275,19.675 ; 131.275,21.3 v2@131.275,21.675 ; 131.275,23.3 v2@131.275,23.675
  Signal Layer 3 w0.635: v2(131.3,19.7) v2(131.3,21.7) v2(131.3,23.7) 131.3,25.655 134.169,28.524 141.6,28.524
  Bottom Layer w0.381: v2(131.3,19.7) v2(131.3,21.7) v2(131.3,23.7)
  Bottom Layer w1.016: 24.4,1.3 24.6,1.3 26.3,3 27.8,1.5 28,1.5 ; 26.3,3.2 D19.1@26.3,4.9 ; X7.P8@128.75,49.855 130.727,49.855 ; 131.472,49.11 130.727,49.855 ; 131.472,50.6 130.727,49.855
  Bottom Layer w1.6: 4.423,20.9 5.423,21.9 ; 4.423,22.9 5.423,21.9 ; D10.3@9,21.9 5.423,21.9
  other v1: 10,1 20,1 30,1 40,1 50,1 60,1 70,1 80,1 90,1 100,1 110,1 120,1 130,1 135.6,8.5 136.3,8.5 138.3,8.5 139,8.5 141,8.5 141.7,8.5 144,11 1,21 144,21 144,31 1,41 144,41 139,46 14,46.4 14.7,46.4 6.1,47.8 6.8,47.8 8.8,47.8 9.5,47.8 11.4,47.8 12.1,47.8 1,51 134,51 144,51 134,56 139,56 1,61 144,61 134,66 139,66 10,74 20,74 30,74 40,74 50,74 60,74 70,74 80,74 90,74 100,74 110,74 120,74 130,74
  other v4: 4,1.7 141,1.7 2.374,2.374 5.626,2.374 139.374,2.374 142.626,2.374 1.7,4 6.3,4 138.7,4 143.3,4 2.374,5.626 5.626,5.626 139.374,5.626 142.626,5.626 4,6.3 141,6.3 4,28.4 2.374,29.074 5.626,29.074 1.7,30.7 6.3,30.7 2.374,32.326 5.626,32.326 4,33 4,68.7 141,68.7 2.374,69.374 5.626,69.374 139.374,69.374 142.626,69.374 1.7,71 6.3,71 138.7,71 143.3,71 2.374,72.626 5.626,72.626 139.374,72.626 142.626,72.626 4,73.3 141,73.3
TEST: IC1.34 R12.1 | length 8.8
  Top Layer w0.203: IC1.34@116.8,22.85 122.895,22.85 123.225,23.18 124.251,23.18 R12.1@125.125,24.055
TR0_N: IC1.2 R161.1 X8.3 | length 24.7
  Top Layer w0.154: v2(102.68,24.459) 103.04,24.459 103.201,24.619 107.524,24.619 108.684,23.46 109.463,23.46 109.573,23.35 IC1.2@110,23.35
  Top Layer w0.381: v3(97.158,19.976) X8.3@98.74,19.976
  Bottom Layer w0.154: v3(97.158,19.976) 97.158,18.992 97.406,18.744 98.07,18.744 99.226,19.9 103.303,19.9 103.719,20.316 103.719,24.481 103.582,24.618 103.2,24.618 103.04,24.459 v2(102.68,24.459)
  Bottom Layer w0.254: R161.1@95.65,19.9 95.726,19.976 v3(97.158,19.976)
TR0_P: IC1.1 R160.1 X8.1 | length 24.9
  Top Layer w0.154: v2(102.68,25.058) 103.041,25.058 103.2,24.9 107.64,24.9 108.8,23.74 109.463,23.74 109.573,23.85 IC1.1@110,23.85
  Top Layer w0.381: v3(97.158,17.436) X8.1@98.74,17.436
  Bottom Layer w0.154: v3(97.158,17.436) 99.342,19.619 103.419,19.619 104,20.2 104,24.597 103.698,24.899 103.201,24.899 103.041,25.058 v2(102.68,25.058)
  Bottom Layer w0.254: R160.1@95.65,17.4 95.686,17.436 v3(97.158,17.436)
TR1_N: IC1.5 R163.1 X8.8 | length 21.3
  Top Layer w0.154: v2(101.079,22.046) 101.44,22.046 101.6,22.206 107.397,22.206 107.643,21.96 109.463,21.96 109.573,21.85 IC1.5@110,21.85
  Top Layer w0.381: v3(97.158,26.326) X8.8@98.74,26.326
  Bottom Layer w0.154: v3@97.142,26.31 99.521,23.931 102.116,23.931 102.481,23.566 102.481,22.594 102.092,22.206 101.599,22.206 101.439,22.046 v2(101.079,22.046)
  Bottom Layer w0.254: R163.1@95.65,26.37 95.694,26.326 v3(97.158,26.326)
TR1_P: IC1.4 R162.1 X8.6 | length 21.3
  Top Layer w0.154: v2(101.079,22.646) 101.44,22.646 101.599,22.488 ; 101.6,22.486 107.514,22.486 107.76,22.24 109.463,22.24 109.573,22.35 IC1.4@110,22.35
  Top Layer w0.381: v3(97.158,23.786) X8.6@98.74,23.786
  Bottom Layer w0.154: v3(97.158,23.786) 97.172,23.8 97.172,24.992 97.381,25.2 97.855,25.2 99.405,23.65 102,23.65 102.2,23.45 102.2,22.711 101.976,22.486 101.6,22.486 101.44,22.646 v2(101.079,22.646)
  Bottom Layer w0.254: R162.1@95.65,23.9 95.764,23.786 v3(97.158,23.786)
TXA_N: C100.1 IC13.75 R155.1 R161.2 X8.14 | length 60.6
  Top Layer w0.154: v2(107.2,54.2) 107.36,54.36 107.738,54.36 107.848,54.25 IC13.75@108.25,54.25
  Top Layer w0.254: C100.1@86.826,19.2 R155.1@86.826,20.7 87.625,20.7 88.33,19.995 X8.14@89.989,19.995
  Top Layer w0.381: X8.14@90.009,20.014 v3(91.591,20.014)
  Bottom Layer w0.154: v3@91.591,20 90.686,20 90.25,20.436 90.25,25.117 89.2,26.167 89.2,28.6 90.176,29.576 102.526,29.576 105.2,32.25 105.2,53.9 105.66,54.36 106.74,54.36 106.9,54.2 v2(107.2,54.2)
  Bottom Layer w0.254: v3@91.591,20 92.85,20 R161.2@92.95,19.9
TXA_P: C99.1 IC13.76 R154.1 R160.2 X8.16 | length 63
  Top Layer w0.154: v2(107.2,54.8) 107.36,54.64 107.738,54.64 107.848,54.75 IC13.76@108.25,54.75
  Top Layer w0.254: C99.1@86.826,16.2 R154.1@86.826,17.4 ; R154.1@86.826,17.7 R154.1@86.826,17.4 ; X8.16@89.989,17.455 86.881,17.455 R154.1@86.826,17.4
  Top Layer w0.381: X8.16@90.009,17.474 v3(91.591,17.474)
  Bottom Layer w0.154: v3@91.591,17.461 v3(91.591,17.474) 91.591,17.5 91.591,18.645 89.969,20.267 89.969,25.001 88.919,26.051 88.919,28.716 90.059,29.856 102.41,29.856 104.919,32.366 104.919,54.016 105.543,54.64 106.74,54.64 106.9,54.8 v2(107.2,54.8)
  Bottom Layer w0.254: v3@91.591,17.5 92.85,17.5 R160.2@92.95,17.4
TXB_N: C86.1 D26.2 IC13.86 R78.1 X7.P3 | length 29.8
  Top Layer w0.147: IC13.86@108.25,59.75 108.75,59.75 108.799,59.701 108.803,59.704 109.497,59.704 109.5,59.707 ; 110.119,59.707 110.123,59.704 ; 114.831,59.707 115.474,59.064 115.474,55.326 115.7,55.1 D26.2@116.925,55.1 ; D26.2@116.925,55.084 122.174,55.084 122.348,55.084 122.348,55.584 122.695,55.584 122.695,55.084 123.043,55.084 123.043,55.584 123.39,55.584 123.39,55.084 123.737,55.084 123.737,55.584 124.085,55.584 124.085,55.084 124.432,55.084 124.432,55.584 124.779,55.584 124.779,55.084 124.953,55.084 126.046,55.084 126.21,55.248 X7.P3@126.21,56.205
  Top Layer w0.154: 109.5,59.707 v2(109.66,59.867) 109.96,59.867 110.119,59.707 114.831,59.707
  Bottom Layer w0.154: v2(109.66,59.867) 109.992,59.867 110.09,59.964 C86.1@110.09,60.475
  Bottom Layer w0.203: R78.1@124.625,56.205 X7.P3@126.21,56.205
TXB_P: C85.1 D26.8 IC13.85 R77.1 X7.P1 | length 30.8
  Top Layer w0.147: IC13.85@108.25,59.25 108.7,59.25 108.876,59.426 109.5,59.426 ; 114.724,59.426 115.2,58.95 115.2,55.212 115.712,54.7 D26.8@117.875,54.7 118.65,54.7 118.76,54.81 126.285,54.81 127.2,55.725 127.2,57.755 X7.P1@126.21,58.745
  Top Layer w0.154: 109.5,59.426 v2(109.66,59.267) 109.96,59.267 110.119,59.426 114.719,59.426 114.721,59.424
  Bottom Layer w0.154: v2(109.66,59.267) 110.067,59.267 C85.1@111.2,60.4
  Bottom Layer w0.203: R77.1@124.625,58.7 126.165,58.7 X7.P1@126.21,58.745
USB2D1_N: D4.2 D4.5 L5.4 X1.A7 X1.B7 | length 8.7
  Top Layer w0.206: L5.4@128.85,21.1 129.154,21.1 129.454,20.8 130.425,20.8 131.375,20.8 133.667,20.8 133.717,20.85 X1.A7@134.42,20.85
  Bottom Layer w0.206: v2(132.923,20.884) 133.646,20.884 134.053,20.478 134.879,20.478 135.156,20.2 X1.B7@135.67,20.2
USB2D1_P: D4.1 D4.6 L5.1 X1.A6 X1.B6 | length 10.2
  Top Layer w0.206: L5.1@128.85,20.1 129.14,20.1 129.44,20.4 133.667,20.4 133.717,20.35 X1.A6@134.42,20.35
  Bottom Layer w0.206: v2@132.36,20.325 132.36,21.113 132.589,21.341 133.66,21.341 134.18,20.821 134.994,20.821 135.173,21 X1.B6@135.67,21
  other v2: 132.415,20.325
USB2D_N: IC1.27 L5.3 | length 11.3
  Top Layer w0.206: IC1.27@116.8,19.35 117.253,19.35 117.336,19.266 117.989,19.266 118.9,18.355 122.6,18.355 v2(122.8,18.555) ; v2@124.3,20.721 125.466,20.721 125.8,21.055 L5.3@126.05,21.055
  Bottom Layer w0.206: v2(122.8,18.555) 123.015,18.555 123.457,18.998 123.457,19.912 v2(124.3,20.755)
USB2D_P: IC1.26 L5.2 | length 11.4
  Top Layer w0.206: IC1.26@116.8,18.85 117.253,18.85 117.337,18.934 117.851,18.934 118.762,18.022 v2@123.2,18.022 ; v2(124.5,20.155) 124.734,20.389 125.466,20.389 125.8,20.055 L5.2@126.05,20.055
  Bottom Layer w0.206: v2(123.2,18.055) 123.2,18.27 123.79,18.86 123.79,19.755 124.19,20.155 v2(124.5,20.155)
USB3RX1_N: D3.2 D3.5 L3.4 X1.B11 | length 19
  Top Layer w0.206: L3.4@129.025,22.956 129.353,22.956 129.509,22.8 v2@132.324,22.8
  Signal Layer 3 w0.206: v2(132.415,22.891) 132.713,22.891 134.113,24.29 136.045,24.29 136.402,23.933 138.934,23.933 139.318,23.548 139.318,18.943 138.793,18.418 137.118,18.418 136.9,18.2 X1.B11@136.37,18.2
USB3RX1_P: D3.1 D3.6 L3.1 X1.B10 | length 19.8
  Top Layer w0.206: L3.1@129.025,22.206 129.353,22.206 129.547,22.4 131.375,22.4 v2@132.928,22.4
  Signal Layer 3 w0.206: v2(132.923,22.332) 132.923,22.63 134.25,23.957 135.907,23.957 136.264,23.6 138.796,23.6 138.986,23.411 138.986,22.6 138.862,22.477 138.601,22.477 138.478,22.353 138.478,22.189 138.601,22.065 138.862,22.065 138.986,21.942 138.986,21.777 138.862,21.654 138.601,21.654 138.478,21.53 138.478,21.366 138.601,21.242 138.862,21.242 138.986,21.119 138.986,21.036 138.986,19.081 138.655,18.75 137.15,18.75 136.9,19 X1.B10@136.37,19
USB3RX_N: IC1.32 L3.3 | length 12.7
  Top Layer w0.206: IC1.32@116.8,21.85 117.253,21.85 117.336,21.766 123.711,21.766 123.925,21.98 ; 127.547,22.936 L3.3@127.875,22.936 ; L3.3@127.9,22.936 127.572,22.936 127.347,22.711 124.656,22.711 124.425,22.48 ; 123.925,21.98 124.425,22.48 ; 123.925,21.98 124.425,22.48
USB3RX_P: IC1.31 L3.2 | length 12.3
  Top Layer w0.206: IC1.31@116.8,21.35 117.253,21.35 117.337,21.434 123.849,21.434 124.063,21.647 ; L3.2@127.9,22.186 127.572,22.186 127.38,22.378 124.793,22.378 124.563,22.147 ; 124.063,21.647 124.563,22.147 ; 124.063,21.647 124.563,22.147
USB3TX1_N: D2.2 D2.5 L2.4 X1.A3 | length 5.5
  Top Layer w0.206: L2.4@128.97,18.975 129.298,18.975 129.473,18.8 130.37,18.8 131.32,18.8 133.612,18.8 133.662,18.85 X1.A3@134.365,18.85
USB3TX1_P: D2.1 D2.6 L2.1 X1.A2 | length 5.5
  Top Layer w0.206: L2.1@128.97,18.225 129.298,18.225 129.473,18.4 130.37,18.4 131.32,18.4 133.612,18.4 133.662,18.35 X1.A2@134.365,18.35
USB3TX_N: C7.2 IC1.29 | length 9.8
  Top Layer w0.206: IC1.29@116.8,20.35 117.253,20.35 117.336,20.266 118.439,20.266 119.105,19.6 123.599,19.6 124.589,18.61 124.972,18.61 125.372,19.01 C7.2@125.725,19.01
